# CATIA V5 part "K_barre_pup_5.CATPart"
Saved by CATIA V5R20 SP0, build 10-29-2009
Part number: barre_pup_5
Bounding box of the stored display mesh (mm): x -76.409 to -50.386, y -211.469 to -206.469, z -161.421 to 42.168
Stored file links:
  G:\Khaled_CFAO_2011\ST2M\ST2M_GR2\gcausse\Khaled\CAD_ThinkMotion\K_barre_pup_5.CATPart
  C:\Documents and Settings\gcausse\Bureau\video thinkmotio\assemblage_gcausse\pupitre_think.CATProduct
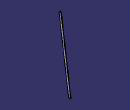
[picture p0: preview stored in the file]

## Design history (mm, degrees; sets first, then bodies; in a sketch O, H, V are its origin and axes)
Set1
  Sketch1 on Plane1, origin (-54.7303, 0, 6.7329), H (0, 1, 0), V (0.1221, 0, 0.9925)
    line L1 (-206.4691, 33.0788) -> (-206.4691, -166.9212)
    arc A1 centre (-208.9691, -166.9212) radius 2.5 from (-206.4691, -166.9212) to (-211.4691, -166.9212) cw
    point P3 (-208.9691, -166.9212)
    line L2 (-211.4691, -166.9212) -> (-211.4691, 33.0788)
    arc A2 centre (-208.9691, 33.0788) radius 2.5 from (-211.4691, 33.0788) to (-206.4691, 33.0788) cw
    point P6 (-208.9691, 33.0788)
    reference projected point E1 (-208.9691, -166.9212) from Point1
    reference projected point E2 (-208.9691, 33.0788) from Point2
    reference projected line E3 (-208.9691, 33.0788) -> (-208.9691, -166.9212) from Line1
    distance L1 L2 = 5
    tangency: A1 L1, L2 A1, A2 L1, A2 L2
    coincidence: P3 E1, P6 E2
    parallelism: L2 E3
Set2
  Plane1: linked copy from another document
  Point1: linked copy from another document
  Point2: linked copy from another document
  Line1: linked copy from another document
Body1 (main body)
  Pad1: profile Sketch1, direction (0.9925, 0, -0.1221), length -1
  Sketch2 on end face of Pad1, origin (-53.0777, -208.1978, 28.3572), H (0.1221, 0, 0.9925), V (0, 1, 0)
    point P1 (11.4145, -0.7713)
    reference projected point E1 (11.4145, -0.7713) from Point2
    coincidence: P1 E1
  Hole1: placed by Sketch2, at (-51.684, -208.9691, 39.6863) direction (0.9925, 0, -0.1221), diameter 1, depth 1
  Sketch3 on end face of Pad1, origin (-74.5404, -210.6191, -146.109), H (0.1221, 0, 0.9925), V (0, 1, 0)
    point P1 (-12.8041, 1.65)
    reference projected point E1 (-12.8041, 1.65) from Point1
    coincidence: P1 E1
  Hole2: placed by Sketch3, at (-76.1038, -208.9691, -158.8173) direction (0.9925, 0, -0.1221), diameter 1, depth 1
